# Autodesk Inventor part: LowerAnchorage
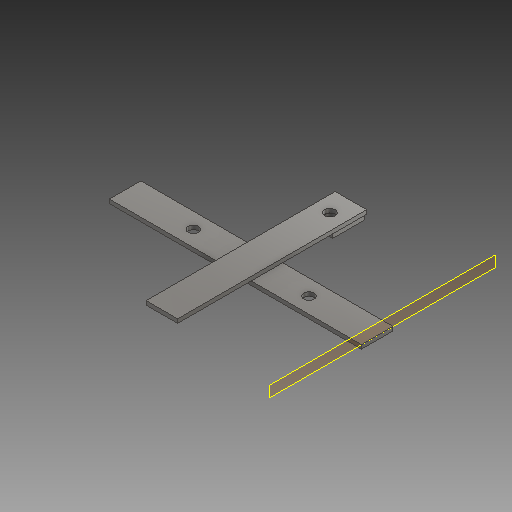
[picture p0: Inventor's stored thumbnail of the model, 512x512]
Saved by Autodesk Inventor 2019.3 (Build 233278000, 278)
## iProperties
Created: 2019-06
Part Number: LowerAnchorage
Material: Steel, Galvanized
Document SubType Name: Modeling
Designer: u1426
Density: 7.85 g/cm^3
Appearance: Galvanized
Author: u1426
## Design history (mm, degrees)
sketch "Sketch11"
  geometry: L1 (38.1, 0)-(-38.1, 0); L2 (-38.1, 0)-(-38.1, -9.525); L3 (-38.1, -9.525)-(38.1, -9.525); L4 (38.1, -9.525)-(38.1, 0); 1 further point
  constraints: 8 end point, 2 horizontal, 1 vertical
  dimensions: "d116" = 76.2 distance of L1.start L1.end; "d117" = 9.525 distance of L1.end L2.end; "d118" = 76.2 distance of L2.end L3.end; "d156" = 38.1 distance from line of point (0, 0) L4
extrude "Extrusion8" new body sketch "Sketch11" distance "d119" = 457.2; taper "d120" = 0 deg
workplane "Work Plane2"
sketch "Sketch13"
  geometry: L1 (19.05, 374.65)-(19.05, 450.85); L2 (19.05, 450.85)-(9.525, 450.85); L3 (9.525, 450.85)-(9.525, 374.65); L4 (9.525, 374.65)-(19.05, 374.65); 2 further points
  constraints: 8 end point, 2 vertical, 1 horizontal
  dimensions: "d129" = 76.2 distance of L1.start L1.end; "d130" = 9.525 distance of L1.end L2.end; "d131" = 76.2 distance of L2.end L3.end; "d133" = 6.35 distance from line of point (0, 457.2) L2
extrude "Extrusion10" new body sketch "Sketch13" distance "d134" = 76.2; taper "d135" = 0 deg
sketch "Sketch14"
  geometry: L1 (0, 457.2)-(0, 0) reference; L2 (19.05, 254)-(9.525, 254); L3 (9.525, 254)-(9.525, 177.8); L4 (9.525, 177.8)-(19.05, 177.8); L5 (19.05, 177.8)-(19.05, 254); 1 further point
  constraints: 8 end point, 2 horizontal, 2 vertical
  dimensions: "d137" = 9.525 distance of L2.start L2.end; "d138" = 76.2 distance of L2.end L3.end; "d139" = 203.2 distance from line of L1.start L2
extrude "Extrusion11" new body sketch "Sketch14" distance "d140" = 609.6; taper "d141" = 0 deg
sketch "Sketch15"
  geometry: L1 (-342.9, 196.85)-(-342.9, 273.05) reference; L2 (-266.7, 196.85)-(-342.9, 196.85) reference; L3 (0, 0)-(-609.6, 0) reference; L4 (-609.6, 0)-(-609.6, 76.2) reference; L5 (0, 76.2)-(0, 0) reference; L6 (-266.7, 279.4)-(-342.9, 279.4) reference; 4 further points
  dimensions: "d149" = 38.1 distance from line of point (-304.8, 228.6) L1; "d151" = 38.1 distance from line of point (-444.5, 38.1) L3; "d152" = 38.1 distance from line of point (-165.1, 38.1) L3; "d153" = 165.1 distance from line of point (-444.5, 38.1) L4; "d154" = 165.1 distance from line of point (-165.1, 38.1) L5; "d157" = 50.8 distance from line of point (-304.8, 228.6) L6
hole "Hole3" sketch "Sketch15" at (-165.1, 38.1), (-444.5, 38.1), (-304.8, 228.6) diameter "d142" = 25.4; stored, may be unused: countersink angle "d146" = 82 deg, drill point angle "d148" = 118 deg; dims "d143" = 19.05, "d144" = 9.525, "d145" = 6.35, "d147" = 25.4
body "Solid6"
body "Solid7"
body "Solid8"
other parameters: "sa_0" = 4, "d128" = 266.7
